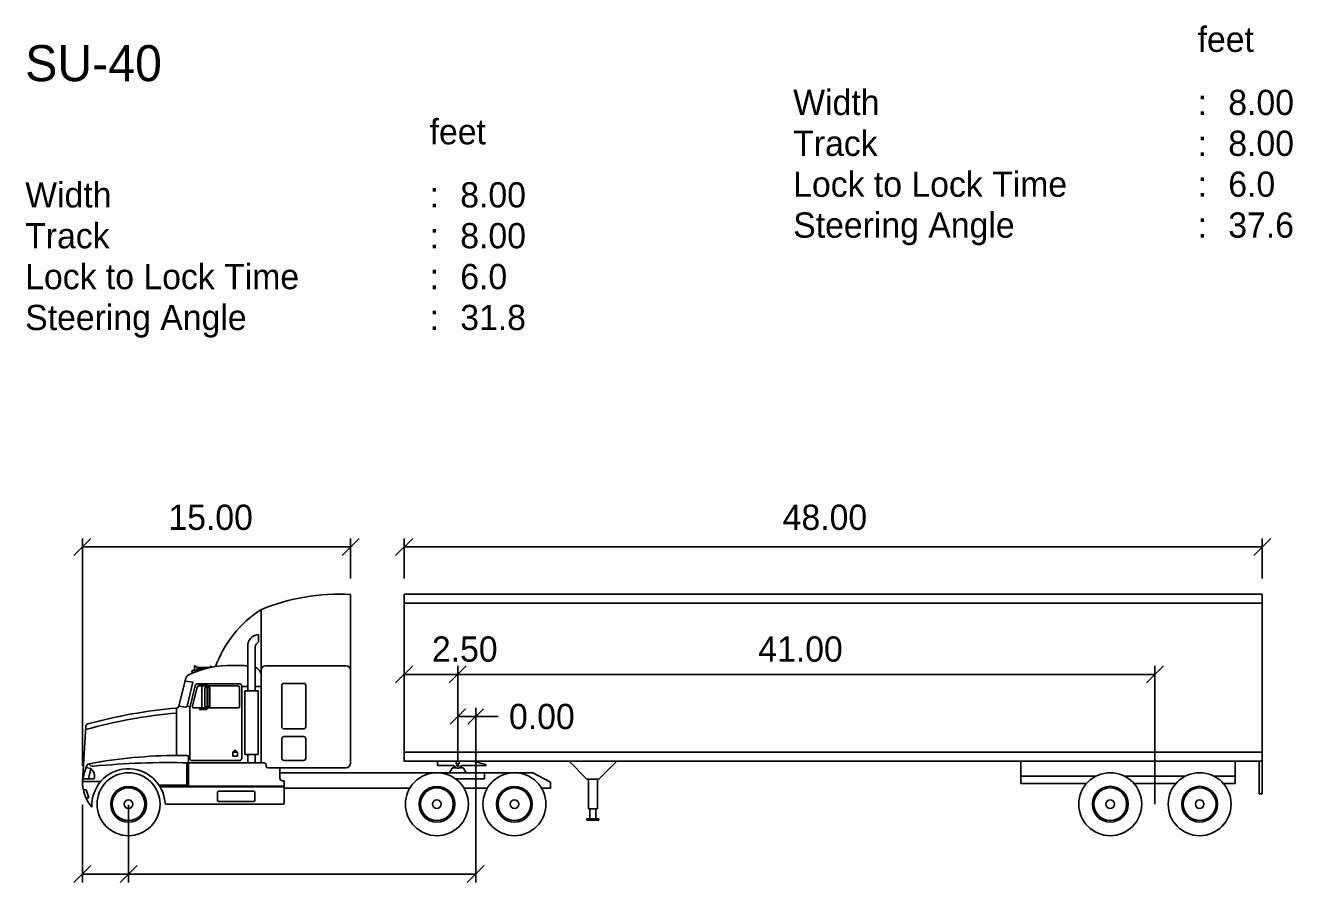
# Model space of a CAD drawing. Extents: x 2297881 to 2300600, y 559917 to 564426.
# Drawn here: x 2299075.6 to 2299141.5, y 562595.9 to 562640.5 of the extents above; entities that cross this region are included whole.
import ezdxf

# ---------------------------------------------------------------- set-up
doc = ezdxf.new("R2010")
doc.units = 0
doc.layers.add('DR_X_Elev_Flow', color=7, linetype='Continuous')

msp = doc.modelspace()

# ---------------------------------------------------------------- linework, layer by layer
at = {"layer": 'DR_X_Elev_Flow'}
for p, q in [((2299078.11, 562612.95), (2299078.996, 562613.836)), ((2299078.553, 562602.023), (2299078.553, 562613.836)), ((2299092.05, 562612.95), (2299092.936, 562613.836)), ((2299092.493, 562611.753), (2299092.493, 562613.836)), ((2299094.837, 562612.95), (2299095.722, 562613.836)), ((2299095.28, 562611.753), (2299095.28, 562613.836)), ((2299139.444, 562612.95), (2299140.329, 562613.836)), ((2299139.886, 562611.753), (2299139.886, 562613.836)), ((2299092.493, 562613.393), (2299078.553, 562613.393)), ((2299139.886, 562613.393), (2299095.28, 562613.393)), ((2299092.493, 562606.983), (2299092.493, 562610.918)), ((2299139.886, 562610.932), (2299095.28, 562610.932)), ((2299095.28, 562602.259), (2299095.28, 562610.932)), ((2299139.886, 562602.259), (2299139.886, 562610.932)), ((2299139.886, 562610.468), (2299095.28, 562610.468)), ((2299087.846, 562606.711), (2299087.846, 562610.135)), ((2299087.714, 562608.454), (2299087.714, 562608.841)), ((2299087.148, 562605.916), (2299087.148, 562608.183)), ((2299087.535, 562605.916), (2299087.535, 562608.183)), ((2299084.267, 562606.967), (2299084.618, 562606.967)), ((2299084.267, 562606.836), (2299084.267, 562606.967)), ((2299084.383, 562607.238), (2299084.52, 562607.122)), ((2299084.383, 562606.967), (2299084.383, 562607.238)), ((2299084.427, 562606.967), (2299084.52, 562607.047)), ((2299084.52, 562607.122), (2299085.174, 562607.122)), ((2299084.52, 562607.047), (2299084.879, 562607.047)), ((2299085.174, 562607.122), (2299085.243, 562607.219)), ((2299085.243, 562607.219), (2299085.243, 562607.132)), ((2299087.846, 562606.711), (2299087.846, 562606.983)), ((2299088.078, 562607.215), (2299092.261, 562607.215)), ((2299092.493, 562606.983), (2299092.493, 562602.151)), ((2299094.837, 562606.323), (2299095.722, 562607.209)), ((2299097.623, 562606.323), (2299098.509, 562607.209)), ((2299098.066, 562602.259), (2299098.066, 562607.209)), ((2299133.867, 562606.323), (2299134.753, 562607.209)), ((2299134.31, 562607.209), (2299134.31, 562600.023)), ((2299083.572, 562605.121), (2299083.916, 562606.514)), ((2299083.893, 562606.421), (2299084.299, 562606.362)), ((2299083.916, 562606.514), (2299083.926, 562606.553)), ((2299083.993, 562605.123), (2299084.299, 562606.362)), ((2299087.846, 562606.711), (2299087.846, 562602.171)), ((2299134.31, 562606.766), (2299095.28, 562606.766)), ((2299084.131, 562605.025), (2299084.416, 562606.181)), ((2299084.274, 562605.121), (2299084.518, 562606.109)), ((2299084.549, 562606.284), (2299086.703, 562606.284)), ((2299084.593, 562606.168), (2299086.646, 562606.168)), ((2299084.636, 562606.207), (2299084.636, 562606.23)), ((2299084.636, 562606.23), (2299084.965, 562606.23)), ((2299084.636, 562606.207), (2299084.965, 562606.207)), ((2299084.768, 562606.168), (2299084.768, 562605.025)), ((2299084.925, 562605.097), (2299084.925, 562606.092)), ((2299084.925, 562606.092), (2299085.17, 562606.092)), ((2299085.043, 562606.13), (2299085.043, 562605.046)), ((2299085.066, 562606.13), (2299085.066, 562605.046)), ((2299085.17, 562606.092), (2299085.17, 562605.097)), ((2299086.723, 562605.102), (2299086.723, 562606.091)), ((2299086.839, 562602.423), (2299086.839, 562606.148)), ((2299086.839, 562606.148), (2299087.148, 562606.148)), ((2299086.993, 562602.602), (2299086.993, 562605.916)), ((2299086.993, 562605.916), (2299087.69, 562605.916)), ((2299087.535, 562606.148), (2299087.846, 562606.148)), ((2299087.69, 562602.602), (2299087.69, 562605.916)), ((2299088.918, 562604.048), (2299088.918, 562606.195)), ((2299089.027, 562606.304), (2299090.05, 562606.304)), ((2299090.159, 562604.048), (2299090.159, 562606.195)), ((2299083.451, 562605.018), (2299083.451, 562602.626)), ((2299083.572, 562605.121), (2299083.917, 562605.071)), ((2299083.993, 562605.123), (2299084.146, 562605.085)), ((2299084.131, 562605.025), (2299084.131, 562602.423)), ((2299084.349, 562605.025), (2299086.646, 562605.025)), ((2299085.17, 562605.097), (2299084.925, 562605.097)), ((2299098.997, 562605.025), (2299098.997, 562595.945)), ((2299084.636, 562604.945), (2299084.636, 562604.968)), ((2299084.965, 562604.968), (2299084.636, 562604.968)), ((2299084.965, 562604.945), (2299084.636, 562604.945)), ((2299097.664, 562604.179), (2299098.469, 562604.984)), ((2299098.066, 562604.582), (2299100.161, 562604.582)), ((2299098.594, 562604.179), (2299099.399, 562604.984)), ((2299078.553, 562601.203), (2299078.738, 562604.079)), ((2299089.027, 562603.939), (2299090.05, 562603.939)), ((2299088.918, 562602.408), (2299088.918, 562603.431)), ((2299089.027, 562603.54), (2299090.05, 562603.54)), ((2299090.159, 562602.408), (2299090.159, 562603.431)), ((2299083.519, 562602.558), (2299084.003, 562602.558)), ((2299084.071, 562602.49), (2299084.071, 562602.171)), ((2299086.375, 562602.732), (2299086.491, 562602.832)), ((2299086.375, 562602.519), (2299086.375, 562602.732)), ((2299086.375, 562602.732), (2299086.607, 562602.732)), ((2299086.375, 562602.519), (2299086.607, 562602.519)), ((2299086.607, 562602.732), (2299086.491, 562602.832)), ((2299086.607, 562602.519), (2299086.607, 562602.732)), ((2299086.993, 562602.602), (2299087.69, 562602.602)), ((2299087.148, 562602.171), (2299087.148, 562602.602)), ((2299087.535, 562602.171), (2299087.535, 562602.602)), ((2299095.28, 562602.723), (2299139.886, 562602.723)), ((2299078.75, 562601.931), (2299078.996, 562601.872)), ((2299078.996, 562601.872), (2299078.872, 562601.347)), ((2299083.984, 562602.171), (2299083.984, 562601.007)), ((2299084.071, 562602.171), (2299084.071, 562601.007)), ((2299087.989, 562602.171), (2299084.071, 562602.171)), ((2299084.267, 562602.287), (2299086.703, 562602.287)), ((2299087.846, 562602.171), (2299087.989, 562602.171)), ((2299088.098, 562602.061), (2299088.098, 562602.028)), ((2299088.207, 562601.919), (2299088.814, 562601.919)), ((2299088.814, 562601.919), (2299092.261, 562601.919)), ((2299088.814, 562601.919), (2299088.814, 562601.378)), ((2299089.027, 562602.299), (2299090.05, 562602.299)), ((2299095.28, 562602.259), (2299139.886, 562602.259)), ((2299097.017, 562602.259), (2299097.017, 562602.042)), ((2299097.017, 562602.259), (2299098.834, 562602.259)), ((2299097.017, 562602.042), (2299097.799, 562602.042)), ((2299097.636, 562601.648), (2299097.779, 562601.897)), ((2299097.813, 562601.917), (2299097.976, 562601.917)), ((2299097.833, 562601.917), (2299097.919, 562601.985)), ((2299097.99, 562602.259), (2299097.99, 562602.126)), ((2299097.99, 562602.126), (2299098.145, 562602.126)), ((2299098.145, 562602.259), (2299098.145, 562602.126)), ((2299098.322, 562601.917), (2299098.159, 562601.917)), ((2299098.302, 562601.917), (2299098.216, 562601.985)), ((2299098.336, 562602.042), (2299099.531, 562602.042)), ((2299098.5, 562601.648), (2299098.356, 562601.897)), ((2299098.834, 562602.259), (2299099.531, 562602.085)), ((2299104.783, 562601.329), (2299103.854, 562602.259)), ((2299105.402, 562601.329), (2299106.332, 562602.259)), ((2299127.33, 562601.097), (2299127.33, 562602.259)), ((2299138.482, 562601.097), (2299138.482, 562602.259)), ((2299139.732, 562600.559), (2299139.732, 562602.259)), ((2299139.886, 562602.259), (2299139.886, 562600.559)), ((2299078.553, 562601.203), (2299079.467, 562601.203)), ((2299078.602, 562601.347), (2299079.119, 562601.347)), ((2299088.814, 562601.648), (2299101.964, 562601.648)), ((2299088.95, 562601.241), (2299089.046, 562601.241)), ((2299089.046, 562601.241), (2299089.046, 562600.09)), ((2299096.674, 562601.648), (2299099.462, 562601.648)), ((2299097.955, 562601.339), (2299099.462, 562601.339)), ((2299099.462, 562601.648), (2299099.462, 562601.339)), ((2299101.964, 562601.648), (2299102.879, 562601.162)), ((2299102.879, 562600.864), (2299102.879, 562601.162)), ((2299104.783, 562601.329), (2299105.402, 562601.329)), ((2299104.86, 562599.78), (2299104.86, 562601.329)), ((2299105.325, 562599.78), (2299105.325, 562601.329)), ((2299127.33, 562601.484), (2299131.251, 562601.484)), ((2299127.33, 562601.097), (2299130.753, 562601.097)), ((2299132.723, 562601.484), (2299135.898, 562601.484)), ((2299133.221, 562601.097), (2299135.399, 562601.097)), ((2299137.37, 562601.484), (2299138.482, 562601.484)), ((2299137.868, 562601.097), (2299138.482, 562601.097)), ((2299078.596, 562600.775), (2299078.744, 562600.775)), ((2299078.744, 562600.775), (2299078.885, 562600.345)), ((2299082.531, 562601.007), (2299084.071, 562601.007)), ((2299082.59, 562600.92), (2299089.046, 562600.92)), ((2299084.115, 562600.964), (2299089.046, 562600.964)), ((2299085.581, 562600.226), (2299085.581, 562600.631)), ((2299085.649, 562600.699), (2299087.449, 562600.699)), ((2299087.517, 562600.226), (2299087.517, 562600.631)), ((2299089.046, 562600.864), (2299095.58, 562600.864)), ((2299098.386, 562600.864), (2299099.608, 562600.864)), ((2299102.413, 562600.864), (2299102.879, 562600.864)), ((2299139.886, 562600.559), (2299139.732, 562600.559)), ((2299078.553, 562599.984), (2299078.553, 562595.945)), ((2299078.737, 562600.345), (2299078.885, 562600.345)), ((2299080.952, 562599.984), (2299080.952, 562595.945)), ((2299082.914, 562600.022), (2299088.978, 562600.022)), ((2299085.649, 562600.157), (2299087.449, 562600.157)), ((2299104.86, 562599.78), (2299105.325, 562599.78)), ((2299104.938, 562599.262), (2299104.938, 562599.78)), ((2299105.248, 562599.262), (2299105.248, 562599.78)), ((2299104.783, 562599.262), (2299105.402, 562599.262)), ((2299104.783, 562599.185), (2299104.783, 562599.262)), ((2299104.783, 562599.185), (2299105.402, 562599.185)), ((2299105.402, 562599.185), (2299105.402, 562599.262)), ((2299078.11, 562595.945), (2299078.996, 562596.831)), ((2299080.509, 562595.945), (2299081.395, 562596.831)), ((2299098.554, 562595.945), (2299099.44, 562596.831)), ((2299078.553, 562596.388), (2299098.997, 562596.388))]:
    msp.add_line(p, q, dxfattribs=at)
for centre, radius in [((2299098.068, 562602.042), 0.0483), ((2299080.952, 562600.022), 1.636), ((2299096.983, 562600.022), 1.636), ((2299101.01, 562600.022), 1.636), ((2299131.987, 562600.023), 1.636), ((2299136.634, 562600.023), 1.636), ((2299080.952, 562600.022), 0.929), ((2299080.952, 562600.022), 0.852), ((2299096.983, 562600.022), 0.929), ((2299096.983, 562600.022), 0.852), ((2299101.01, 562600.022), 0.929), ((2299101.01, 562600.022), 0.852), ((2299131.987, 562600.023), 0.929), ((2299131.987, 562600.023), 0.852), ((2299136.634, 562600.023), 0.929), ((2299136.634, 562600.023), 0.852), ((2299080.952, 562600.022), 0.223), ((2299096.983, 562600.022), 0.223), ((2299101.01, 562600.022), 0.223), ((2299131.987, 562600.023), 0.223), ((2299136.634, 562600.023), 0.223)]:
    msp.add_circle(centre, radius, dxfattribs=at)
for centre, radius, start, end in [((2299091.858, 562600.495), 10.442, 86.51449, 112.66358), ((2299091.029, 562605.16), 5.909, 122.72584, 160.09801), ((2299087.76, 562608.229), 0.614, 94.30168, 184.30168), ((2299087.901, 562608.136), 0.369, 120.51091, 172.63983), ((2299086.214, 562602.187), 5.039, 88.26568, 114.8486), ((2299084.317, 562606.901), 0.0826, 127.09681, 232.90319), ((2299086.68, 562602.595), 4.64, 84.20995, 93.87472), ((2299087.381, 562606.711), 0.465, 0, 70.65942), ((2299088.078, 562606.983), 0.232, 90, 180), ((2299092.261, 562606.983), 0.232, 0, 90), ((2299084.227, 562606.479), 0.31, 114.8486, 166.13031), ((2299084.549, 562606.148), 0.136, 90, 166.13031), ((2299084.593, 562606.091), 0.0774, 90, 166.13031), ((2299084.965, 562606.13), 0.101, 0, 90), ((2299084.965, 562606.13), 0.0774, 0, 90), ((2299086.646, 562606.091), 0.0774, 0, 90), ((2299086.703, 562606.148), 0.136, 0, 90), ((2299089.027, 562606.195), 0.109, 90, 180), ((2299090.05, 562606.195), 0.109, 0, 90), ((2299085.666, 562579.125), 25.987, 94.88958, 105.23315), ((2299083.44, 562605.154), 0.136, 274.87101, 346.13031), ((2299083.927, 562605.139), 0.0682, 261.81221, 346.13031), ((2299084.349, 562605.102), 0.0774, 166.13031, 270), ((2299084.965, 562605.046), 0.101, 270, 0), ((2299084.965, 562605.046), 0.0774, 270, 0), ((2299086.646, 562605.102), 0.0774, 270, 0), ((2299085.667, 562579.118), 25.738, 94.93752, 105.65147), ((2299078.874, 562604.068), 0.136, 105.17625, 175.07289), ((2299089.027, 562604.048), 0.109, 180, 270), ((2299090.05, 562604.048), 0.109, 270, 0), ((2299089.027, 562603.431), 0.109, 90, 180), ((2299090.05, 562603.431), 0.109, 0, 90), ((2299083.621, 562576.576), 25.983, 90.24989, 100.47717), ((2299083.519, 562602.626), 0.0682, 180, 270), ((2299084.003, 562602.49), 0.0682, 0, 90), ((2299084.267, 562602.423), 0.136, 180, 270), ((2299086.491, 562602.832), 0.00545, 0, 180), ((2299086.491, 562602.832), 0.00545, 180, 0), ((2299086.703, 562602.423), 0.136, 270, 0), ((2299089.027, 562602.408), 0.109, 180, 270), ((2299090.05, 562602.408), 0.109, 270, 0), ((2299082.368, 562600.561), 3.869, 157.46737, 170.46027), ((2299078.92, 562601.992), 0.136, 100.43737, 157.46737), ((2299079.106, 562602.229), 0.235, 206.17144, 276.6473), ((2299078.619, 562601.446), 0.569, 356.42186, 48.52195), ((2299080.947, 562599.964), 1.903, 3.62868, 183.08599), ((2299082.974, 562563.195), 38.991, 88.38804, 95.65335), ((2299087.989, 562602.061), 0.109, 0, 90), ((2299088.207, 562602.028), 0.109, 180, 270), ((2299092.261, 562602.151), 0.232, 270, 0), ((2299097.813, 562601.878), 0.0387, 90, 150), ((2299097.799, 562601.887), 0.155, 30, 90), ((2299098.068, 562602.042), 0.155, 210, 330), ((2299098.336, 562601.887), 0.155, 90, 150), ((2299098.322, 562601.878), 0.0387, 30, 90), ((2299099.505, 562602.063), 0.0343, 321.14477, 38.85523), ((2299080.598, 562601.194), 2.046, 179.7708, 220.65601), ((2299079.119, 562601.415), 0.0682, 270, 356.27523), ((2299088.95, 562601.378), 0.136, 180, 270), ((2299084.115, 562601.007), 0.0436, 180, 270), ((2299085.649, 562600.631), 0.0682, 90, 180), ((2299087.449, 562600.631), 0.0682, 0, 90), ((2299082.914, 562600.09), 0.0682, 184.62477, 270), ((2299085.649, 562600.226), 0.0682, 180, 270), ((2299087.449, 562600.226), 0.0682, 270, 0), ((2299088.978, 562600.09), 0.0682, 270, 0)]:
    msp.add_arc(centre, radius, start, end, dxfattribs=at)

# ---------------------------------------------------------------- texts
for s, height, p in [('feet', 1.3123, (2299136.526, 562639.122)), ('SU-40', 1.8748, (2299075.578, 562637.6)), ('Width', 1.3123, (2299115.504, 562635.842)), (':', 1.312, (2299136.526, 562635.842)), ('8.00', 1.3123, (2299138.122, 562635.842)), ('feet', 1.3123, (2299096.601, 562634.319)), ('Track', 1.3123, (2299115.504, 562633.717)), (':', 1.312, (2299136.526, 562633.717)), ('8.00', 1.3123, (2299138.122, 562633.717)), ('Lock to Lock Time', 1.31234, (2299115.504, 562631.592)), ('6.0', 1.3123, (2299138.122, 562631.592)), ('Width', 1.3123, (2299075.578, 562631.038)), (':', 1.312, (2299096.601, 562631.038)), ('8.00', 1.3123, (2299098.196, 562631.038)), (':', 1.312, (2299136.526, 562631.592)), ('Steering Angle', 1.31234, (2299115.504, 562629.467)), ('37.6', 1.3123, (2299138.122, 562629.467)), ('Track', 1.3123, (2299075.578, 562628.914)), ('8.00', 1.3123, (2299098.196, 562628.914)), (':', 1.312, (2299136.526, 562629.467)), (':', 1.312, (2299096.601, 562628.914)), ('Lock to Lock Time', 1.31234, (2299075.578, 562626.789)), ('6.0', 1.3123, (2299098.196, 562626.789)), (':', 1.312, (2299096.601, 562626.789)), ('Steering Angle', 1.31234, (2299075.578, 562624.664)), (':', 1.312, (2299096.601, 562624.664)), ('31.8', 1.3123, (2299098.196, 562624.664)), ('15.00', 1.3123, (2299083.023, 562614.279)), ('48.00', 1.3123, (2299114.958, 562614.279)), ('2.50', 1.3123, (2299096.723, 562607.43)), ('41.00', 1.3123, (2299113.688, 562607.43)), ('0.00', 1.3123, (2299100.73, 562603.926))]:
    msp.add_text(s, height=height, dxfattribs=at).set_placement(p)

doc.saveas('drawing.dxf')
